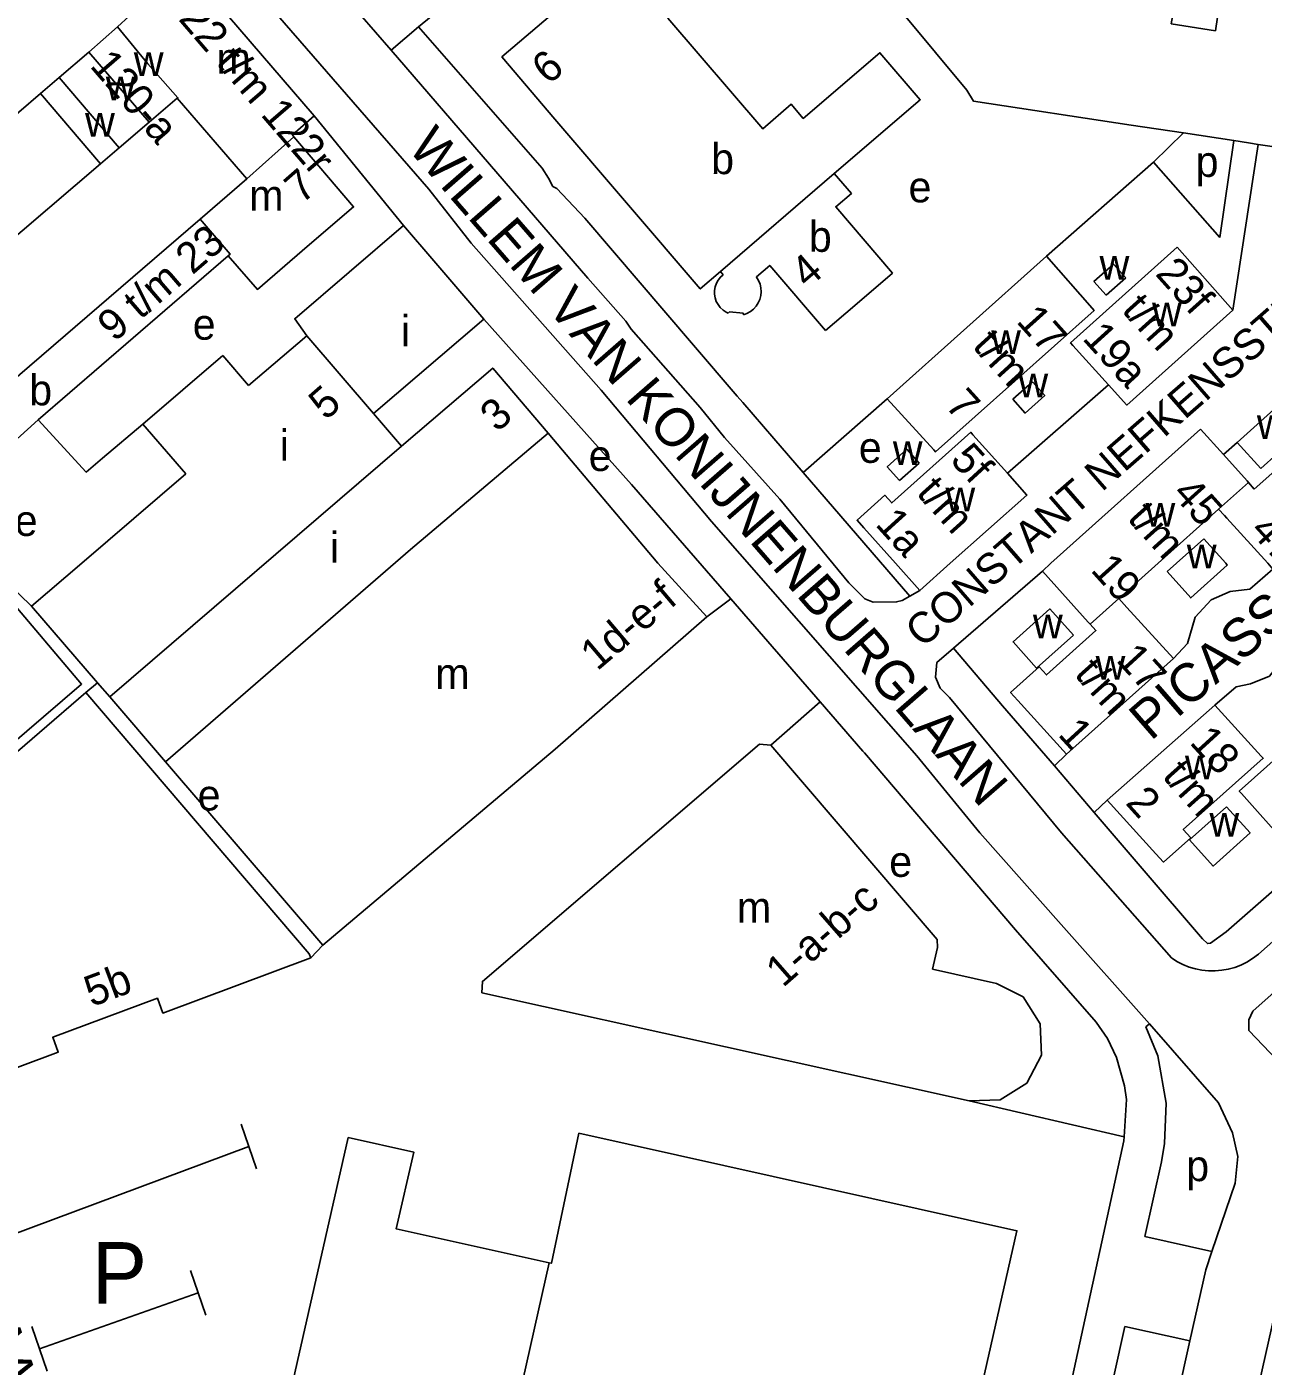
# Model space of a CAD drawing. Extents: x 161775 to 163181, y 382878 to 383925.
# Drawn here: x 162431.4 to 162592, y 383145.8 to 383319.7 of the extents above; entities that cross this region are included whole.
import ezdxf

# ---------------------------------------------------------------- set-up
doc = ezdxf.new("R2010")
doc.units = 0
for name, color, linetype in [('BLT_Basislijn', 7, 'Continuous'), ('BLT_Bebouwing', 7, 'Continuous'), ('BLT_Centroide', 7, 'Continuous'), ('BLT_Huisnummer', 7, 'Continuous'), ('BLT_Huisnummer_reeks', 7, 'Continuous'), ('BLT_Onderdoorgang_en_onderverdeling', 7, 'Continuous'), ('BLT_Onderverdeling_panden', 7, 'Continuous'), ('BLT_Straatnaam', 7, 'Continuous'), ('BLT_Tekst_parkeren', 7, 'Continuous')]:
    doc.layers.add(name, color=color, linetype=linetype)

msp = doc.modelspace()

# ---------------------------------------------------------------- linework, layer by layer
at = {"layer": 'BLT_Basislijn'}
for p, q in [((162478.7, 383316.62), (162482.27, 383319.63)), ((162482.27, 383319.63), (162483.91, 383321.01)), ((162468.7, 383308.09), (162480.34, 383293.87)), ((162581.62, 383305.87), (162577.71, 383302.07)), ((162588.15, 383304.88), (162586.35, 383292.29)), ((162591.33, 383304.39), (162588.01, 383282.86)), ((162563.81, 383289.88), (162577.71, 383302.07)), ((162586.35, 383292.29), (162577.71, 383302.07)), ((162571.86, 383273.18), (162558.75, 383261.69)), ((162528.4, 383266.19), (162524.37, 383270.88)), ((162532.21, 383261.77), (162543.15, 383271.37)), ((162588.58, 383265.7), (162586.81, 383264.11)), ((162532.21, 383261.77), (162546.09, 383245.74)), ((162563.29, 383249), (162551.73, 383238.99)), ((162547.38, 383246.48), (162546.09, 383245.74)), ((162519.72, 383243.06), (162522.82, 383245.41)), ((162440.59, 383234.49), (162439.08, 383233.21)), ((162528.04, 383226.39), (162534.45, 383232)), ((162566.44, 383225.23), (162564.87, 383223.71)), ((162571.72, 383219.27), (162570.01, 383217.65)), ((162469.83, 383200.43), (162468.27, 383198.8)), ((162553.79, 383180.2), (162573.92, 383175.56)), ((162460.22, 383174.28), (162459.22, 383177.17)), ((162460.22, 383174.28), (162429.02, 383162.66)), ((162461.23, 383171.4), (162460.22, 383174.28)), ((162578.75, 383172.29), (162576.61, 383162.62)), ((162576.61, 383162.62), (162585.3, 383160.64)), ((162584.5, 383158.27), (162585.3, 383160.64)), ((162453.66, 383155.3), (162452.65, 383158.19)), ((162582.43, 383149.04), (162584.5, 383158.27)), ((162566.26, 383031.23), (162594.26, 383156.08)), ((162453.66, 383155.3), (162433.05, 383148.01)), ((162454.66, 383152.41), (162453.66, 383155.3)), ((162433.05, 383148.01), (162432.04, 383150.9)), ((162574.02, 383150.93), (162582.43, 383149.04)), ((162434.05, 383145.12), (162433.05, 383148.01)), ((162564.33, 383068.3), (162582.43, 383149.04))]:
    msp.add_line(p, q, dxfattribs=at)
for points in [[(162461.02, 383337.08), (162463.62, 383334.28), (162470.56, 383326.03), (162478.7, 383316.62)], [(162577.2, 383190.23), (162565.75, 383203.12), (162555.18, 383215), (162546.98, 383225), (162520.33, 383255.43), (162505.98, 383272.47), (162489.13, 383291.55), (162483.6, 383298.59), (162460.49, 383325.18), (162458.18, 383327.64), (162456.06, 383330.26)], [(162574.82, 383306.9), (162554.33, 383310), (162553.46, 383311.42), (162545.35, 383321.19), (162545.63, 383322.33), (162548.32, 383324.44), (162552.73, 383328.57), (162552.67, 383329.15), (162551.02, 383331.07)], [(162482.27, 383319.63), (162498.33, 383301.28), (162499.14, 383300.01), (162499.73, 383298.93), (162500.25, 383298.66), (162503.86, 383294.82), (162517.99, 383278.32), (162523.66, 383271.7), (162524.37, 383270.88)], [(162546.09, 383245.74), (162545.09, 383245.18), (162544.36, 383244.99), (162541.31, 383244.97), (162540.22, 383245.4), (162538.15, 383247.47), (162529.18, 383258.32), (162522.03, 383266.33), (162518.84, 383270.23), (162509.9, 383280.38), (162509.2, 383281.43), (162504.26, 383287.03), (162478.7, 383316.62)], [(162581.62, 383305.87), (162574.82, 383306.9)], [(162588.15, 383304.88), (162581.62, 383305.87)], [(162591.33, 383304.39), (162590.04, 383304.6), (162588.15, 383304.88)], [(162595.15, 383303.79), (162594.61, 383303.88), (162591.33, 383304.39)], [(162522.82, 383245.41), (162509.93, 383260.25), (162490.74, 383281.7)], [(162446.49, 383268.07), (162441.22, 383263.66), (162439.71, 383262.34), (162439.11, 383261.84), (162432.86, 383268.63)], [(162528.4, 383266.19), (162532.21, 383261.77)], [(162419.52, 383256.55), (162432.03, 383244.45)], [(162570.01, 383217.65), (162576.23, 383210.37), (162584.08, 383201.25), (162584.73, 383200.63), (162585.13, 383200.67), (162587.16, 383202.14), (162600, 383213.42), (162644.34, 383252.93)], [(162591.34, 383199.25), (162600, 383206.93), (162614.36, 383219.68), (162636.52, 383239.9), (162642.31, 383245.08), (162642.78, 383245.3), (162643.76, 383246.45), (162645.08, 383250.55), (162644.5, 383252.69), (162644.34, 383252.93)], [(162580.33, 383237.65), (162582.12, 383239.57), (162583.14, 383243.01), (162585.21, 383245.27), (162587.69, 383246.34), (162590.24, 383246.63), (162593.23, 383249.26)], [(162534.45, 383232), (162522.82, 383245.41)], [(162598.61, 383243.21), (162594.86, 383239.96), (162594.52, 383237.55), (162592.77, 383235.34), (162590.32, 383234.35), (162588.47, 383233.98), (162585.68, 383231.57)], [(162551.73, 383238.99), (162549.59, 383237.14), (162549.43, 383235.22), (162550.02, 383233.78), (162551.23, 383232.58), (162565.79, 383215), (162580.04, 383198.76)], [(162551.73, 383238.99), (162558.1, 383231.49), (162564.87, 383223.71)], [(162540.18, 383225.4), (162539.99, 383225.63), (162534.45, 383232)], [(162570.27, 383190.42), (162559.78, 383202.42), (162540.18, 383225.4)], [(162564.87, 383223.71), (162570.01, 383217.65)], [(162580.04, 383198.76), (162580.77, 383198.3), (162581.54, 383197.9), (162582.34, 383197.59), (162583.17, 383197.34), (162584.01, 383197.18), (162584.87, 383197.09), (162585.73, 383197.08), (162586.59, 383197.16), (162587.44, 383197.31), (162588.27, 383197.54), (162589.08, 383197.85), (162589.85, 383198.23), (162590.58, 383198.68), (162591.34, 383199.25)], [(162590.09, 383189.33), (162590.09, 383190.72), (162590.62, 383191.84), (162594.57, 383195.37)], [(162573.92, 383175.56), (162574.21, 383180.4), (162573.97, 383182.15), (162572.92, 383185.86), (162571.76, 383188.3), (162570.27, 383190.42)], [(162578.75, 383172.29), (162579.15, 383174.67), (162579.38, 383179.93), (162578.29, 383186.07), (162576.73, 383189.82), (162577.2, 383190.23)], [(162585.3, 383160.64), (162588.31, 383169.51), (162588.68, 383173), (162588, 383176.05), (162586.16, 383179.94), (162577.2, 383190.23)], [(162597.4, 383181.68), (162590.09, 383189.33)], [(162573.92, 383175.56), (162573.88, 383175.03), (162553.06, 383079.48), (162552.67, 383077.71)], [(162574.02, 383150.93), (162557.55, 383076.64), (162556.13, 383070.15)]]:
    msp.add_lwpolyline(points, dxfattribs=at)
at = {"layer": 'BLT_Bebouwing'}
for p, q in [((162443.17, 383319.64), (162439.45, 383316.37)), ((162439.45, 383316.37), (162435.6, 383313.06)), ((162435.6, 383313.06), (162433.18, 383310.99)), ((162433.18, 383310.99), (162385.9, 383270.62)), ((162447.3, 383307.26), (162450.94, 383310.37)), ((162450.94, 383310.37), (162459.98, 383299.91)), ((162443.4, 383303.93), (162447.3, 383307.26)), ((162443.39, 383303.93), (162440.98, 383301.87)), ((162393.7, 383261.49), (162440.98, 383301.87)), ((162459.98, 383299.91), (162453.92, 383294.69)), ((162484.28, 383289.27), (162480.34, 383293.87)), ((162580.78, 383291.04), (162588.01, 383282.86)), ((162432.86, 383268.63), (162457.56, 383289.92)), ((162490.74, 383281.7), (162484.28, 383289.27)), ((162521.83, 383287.47), (162521.49, 383287.87)), ((162574.12, 383287.08), (162571.58, 383284.8)), ((162476.42, 383269.46), (162490.74, 383281.7)), ((162460.18, 383273.08), (162467.75, 383279.55)), ((162571.86, 383273.18), (162567.26, 383278.3)), ((162456.85, 383276.97), (162446.49, 383268.07)), ((162561.99, 383273.58), (162559.44, 383271.3)), ((162476.42, 383269.46), (162480.07, 383265.21)), ((162446.49, 383268.07), (162452.05, 383261.6)), ((162558.75, 383261.69), (162554.28, 383266.68)), ((162596.39, 383266.56), (162591.64, 383262.29)), ((162547.27, 383263.02), (162544.73, 383260.76)), ((162590.07, 383260.48), (162589.88, 383260.7)), ((162590.07, 383260.48), (162590.79, 383259.62)), ((162563.29, 383249), (162569.23, 383242.37)), ((162440.59, 383234.49), (162432.03, 383244.45)), ((162569.23, 383242.37), (162569.49, 383242.09)), ((162567.32, 383240.66), (162562.54, 383236.39)), ((162442.17, 383232.65), (162440.59, 383234.49)), ((162449.42, 383224.21), (162442.17, 383232.65)), ((162585.68, 383231.57), (162591.72, 383224.96)), ((162469.83, 383200.43), (162449.42, 383224.21)), ((162587.19, 383218.4), (162582.41, 383214.12))]:
    msp.add_line(p, q, dxfattribs=at)
for points in [[(162536.26, 383300.63), (162547.42, 383310.18), (162542.19, 383316.28), (162532.24, 383307.77), (162530.68, 383309.59), (162526.97, 383306.42), (162514.67, 383320.79), (162521.99, 383327.05), (162515.43, 383334.72), (162504.4, 383325.36), (162499.99, 383321.61), (162493.11, 383315.75), (162499.99, 383307.67), (162518.87, 383285.63), (162521.49, 383287.87)], [(162468.7, 383308.09), (162452.08, 383327.43), (162444.69, 383321.05), (162443.17, 383319.64)], [(162580.68, 383323.57), (162580.03, 383320.04), (162585.77, 383319.15), (162586.31, 383322.67)], [(162466.09, 383305.38), (162465.89, 383305.62), (162468.7, 383308.09)], [(162466.09, 383305.38), (162473.84, 383296.28), (162467.8, 383291.15), (162461.36, 383285.55), (162457.56, 383289.92)], [(162535.12, 383280.22), (162538.92, 383283.48), (162543.82, 383287.67), (162536.45, 383296.29), (162538.49, 383298.03), (162536.26, 383300.63)], [(162453.92, 383294.69), (162428.95, 383273.17), (162415.49, 383261.1)], [(162480.34, 383293.87), (162466.19, 383281.76), (162467.75, 383279.55)], [(162567.26, 383278.3), (162566.96, 383278.63), (162580.78, 383291.04)], [(162535.12, 383280.22), (162527.89, 383288.68), (162526.15, 383287.2)], [(162563.81, 383289.88), (162543.15, 383271.37)], [(162569.74, 383283.14), (162563.81, 383289.88)], [(162571.58, 383284.8), (162569.99, 383286.57), (162572.53, 383288.85), (162574.12, 383287.08)], [(162521.83, 383287.47), (162521.47, 383287.15), (162521.18, 383286.77), (162520.95, 383286.35), (162520.79, 383285.89), (162520.71, 383285.42), (162520.71, 383284.93), (162520.78, 383284.46), (162520.94, 383284), (162521.17, 383283.58), (162521.46, 383283.2), (162521.82, 383282.87), (162522.22, 383282.61), (162522.5, 383282.48)], [(162524.46, 383282.27), (162524.93, 383282.45), (162525.37, 383282.7), (162525.77, 383283.01), (162526.1, 383283.39), (162526.38, 383283.81), (162526.58, 383284.27), (162526.71, 383284.76), (162526.76, 383285.26), (162526.73, 383285.76), (162526.62, 383286.25), (162526.44, 383286.72), (162526.18, 383287.16), (162526.15, 383287.2)], [(162549.19, 383264.74), (162549.43, 383264.47), (162570, 383282.84), (162569.74, 383283.14)], [(162524.46, 383282.27), (162524.42, 383282.49), (162522.67, 383282.63), (162522.5, 383282.48)], [(162588.01, 383282.86), (162574.24, 383270.54), (162571.86, 383273.18)], [(162456.85, 383276.97), (162460.18, 383273.08)], [(162480.07, 383265.21), (162491.91, 383275.35), (162499.12, 383266.91)], [(162559.44, 383271.3), (162561.04, 383269.51), (162563.59, 383271.79), (162561.99, 383273.58)], [(162543.15, 383271.37), (162549.19, 383264.74)], [(162588.58, 383265.7), (162593.36, 383269.97)], [(162419.52, 383256.55), (162432.86, 383268.63)], [(162583.83, 383267.42), (162564.4, 383250), (162563.29, 383249)], [(162586.81, 383264.11), (162583.83, 383267.42)], [(162590.79, 383259.62), (162600, 383267.81), (162600.87, 383268.59)], [(162499.12, 383266.91), (162513.33, 383250), (162519.72, 383243.06)], [(162554.28, 383266.68), (162553.99, 383267.01), (162543.73, 383257.85), (162542.85, 383258.83), (162539.22, 383255.59), (162540.1, 383254.61)], [(162591.64, 383262.29), (162588.58, 383265.7)], [(162544.73, 383260.76), (162543.14, 383262.54), (162545.68, 383264.8), (162547.27, 383263.02)], [(162589.88, 383260.7), (162586.81, 383264.11)], [(162432.03, 383244.45), (162438.55, 383250), (162452.05, 383261.6)], [(162558.75, 383261.69), (162561.28, 383258.85), (162551.33, 383250), (162547.38, 383246.48)], [(162573.21, 383245.42), (162578.34, 383250), (162586.18, 383257.01)], [(162587.25, 383255.85), (162586.94, 383256.19), (162586.18, 383257.01)], [(162593.23, 383249.26), (162592.56, 383250), (162587.25, 383255.85)], [(162540.1, 383254.61), (162544.22, 383250), (162547.38, 383246.48)], [(162584.26, 383253.18), (162587.11, 383250), (162587.3, 383249.78), (162582.55, 383245.5), (162579.49, 383248.92)], [(162579.49, 383248.92), (162580.7, 383250), (162584.26, 383253.18)], [(162407.68, 383229.67), (162428.77, 383245.83), (162438.52, 383234.33), (162426.43, 383223.98), (162417.76, 383220.74), (162413.7, 383226.17), (162410.59, 383223.58)], [(162580.33, 383237.65), (162574.28, 383244.26), (162573.21, 383245.42)], [(162519.72, 383243.06), (162500, 383225.87), (162469.83, 383200.43)], [(162562.54, 383236.39), (162559.49, 383239.8), (162564.26, 383244.08), (162567.32, 383240.66)], [(162569.49, 383242.09), (162570.24, 383241.26), (162563.81, 383235.51), (162562.87, 383236.56), (162559.17, 383233.25), (162560.11, 383232.21)], [(162589.13, 383220.13), (162588.85, 383220.44), (162600, 383230.39), (162609.46, 383238.83), (162609.73, 383238.54)], [(162609.73, 383238.54), (162615.63, 383231.92), (162600, 383217.85), (162595.1, 383213.44), (162589.13, 383220.13)], [(162566.44, 383225.23), (162580.33, 383237.65)], [(162439.08, 383233.21), (162426.99, 383222.86), (162413.28, 383217.74)], [(162439.08, 383233.21), (162468.07, 383199.32), (162468.27, 383198.8)], [(162560.11, 383232.21), (162566.44, 383225.23)], [(162571.72, 383219.27), (162585.68, 383231.57)], [(162528.04, 383226.39), (162526.55, 383226.51), (162490.56, 383195.73), (162490.51, 383194.23)], [(162549.61, 383201.17), (162528.04, 383226.39)], [(162591.72, 383224.96), (162591.97, 383224.69), (162581.58, 383215.46), (162582.55, 383214.36), (162579.01, 383211.21), (162578.02, 383212.3)], [(162578.02, 383212.3), (162571.72, 383219.27)], [(162582.41, 383214.12), (162585.48, 383210.69), (162590.26, 383215), (162587.19, 383218.4)], [(162549.04, 383197.33), (162549.65, 383200.11), (162549.61, 383201.17)], [(162468.27, 383198.8), (162449.07, 383191.61), (162448.37, 383193.54), (162434.78, 383188.48), (162435.49, 383186.53), (162416.23, 383179.36), (162415.91, 383180.22), (162412.51, 383178.96), (162414.96, 383172.53), (162408.57, 383170.14), (162409.86, 383166.74), (162410.67, 383167.05), (162417.84, 383147.83), (162415.94, 383147.11), (162417.14, 383143.88)], [(162553.79, 383180.2), (162557.83, 383180.34), (162561.28, 383182.53), (162563.17, 383186.16), (162562.99, 383190.23), (162560.78, 383193.7), (162557.33, 383195.47), (162549.04, 383197.33)], [(162490.51, 383194.23), (162553.79, 383180.2)], [(162484.41, 383093.3), (162476.63, 383095.06), (162472.81, 383096.58), (162469.69, 383099.12), (162467.59, 383102.47), (162466.61, 383106.34), (162466.85, 383110.32), (162467.23, 383111.98), (162459.16, 383113.79), (162473.14, 383175.45), (162481.65, 383173.57), (162479.35, 383163.61), (162499.25, 383159.18)], [(162541.22, 383080.46), (162559.99, 383163.35), (162503.1, 383176.01), (162499.52, 383159.12), (162499.25, 383159.18)]]:
    msp.add_lwpolyline(points, dxfattribs=at)
at = {"layer": 'BLT_Onderdoorgang_en_onderverdeling'}
for p, q in [((162435.6, 383313.06), (162443.4, 383303.93)), ((162433.18, 383310.99), (162440.98, 383301.87))]:
    msp.add_line(p, q, dxfattribs=at)
at = {"layer": 'BLT_Onderverdeling_panden'}
for p, q in [((162447.13, 383314.84), (162443.17, 383319.64)), ((162447.3, 383307.26), (162439.45, 383316.37)), ((162466.09, 383305.38), (162459.98, 383299.91)), ((162536.26, 383300.63), (162521.49, 383287.87)), ((162467.75, 383279.55), (162476.42, 383269.46)), ((162442.17, 383232.65), (162480.07, 383265.21)), ((162586.18, 383257.01), (162590.07, 383260.48)), ((162569.49, 383242.09), (162573.21, 383245.42)), ((162499.25, 383159.18), (162484.41, 383093.3))]:
    msp.add_line(p, q, dxfattribs=at)
for points in [[(162450.94, 383310.37), (162451.03, 383310.45), (162447.13, 383314.84)], [(162453.92, 383294.69), (162457.83, 383290.15), (162457.56, 383289.92)], [(162499.12, 383266.91), (162481.23, 383251.8), (162449.42, 383224.21)]]:
    msp.add_lwpolyline(points, dxfattribs=at)

# ---------------------------------------------------------------- texts
at = {"layer": 'BLT_Centroide'}
for s, p in [('w', (162445.3, 383313.27)), ('m', (162456.05, 383313.55)), ('w', (162441.66, 383310.12)), ('w', (162438.97, 383305.38)), ('b', (162520.27, 383300.53)), ('p', (162583.19, 383300.17)), ('m', (162460.28, 383295.78)), ('e', (162545.91, 383296.86)), ('b', (162532.96, 383290.44)), ('w', (162570.72, 383286.81)), ('w', (162577.53, 383280.78)), ('e', (162452.95, 383279.03)), ('i', (162479.99, 383278.19)), ('w', (162556.64, 383277.19)), ('b', (162431.71, 383270.51)), ('w', (162560.17, 383271.53)), ('w', (162591.15, 383266.12)), ('i', (162464.25, 383263.34)), ('e', (162539.45, 383263.04)), ('w', (162543.87, 383262.78)), ('e', (162504.37, 383261.98)), ('w', (162550.7, 383256.75)), ('w', (162576.68, 383254.75)), ('e', (162429.83, 383253.55)), ('i', (162470.75, 383250.09)), ('w', (162582.05, 383249.34)), ('w', (162562.07, 383240.25)), ('w', (162570.2, 383234.91)), ('m', (162484.45, 383233.69)), ('w', (162581.81, 383221.94)), ('e', (162453.59, 383217.91)), ('w', (162584.99, 383214.53)), ('e', (162543.4, 383209.29)), ('m', (162523.62, 383203.34)), ('p', (162581.97, 383169.79))]:
    msp.add_text(s, height=4, dxfattribs=at).set_placement(p)
at = {"layer": 'BLT_Huisnummer'}
for s, rotation, p in [('6', 40.4039, (162499.15, 383312.02)), ('7', 41.1871, (162467.1, 383296.55)), ('4', 40.5479, (162532.79, 383285.57)), ('5', 41.1871, (162470.23, 383268.46)), ('3', 41.1871, (162492.49, 383266.91))]:
    msp.add_text(s, height=4, rotation=rotation, dxfattribs=at).set_placement(p)
at = {"layer": 'BLT_Huisnummer_reeks'}
for s, rotation, p in [('122 t/m 122r', 310.7566, (162449.05, 383322.86)), ('120-a', 310.7571, (162439.47, 383314.54)), ('9 t/m 23', 40.7579, (162442.77, 383278.64)), ('23f', 311.8068, (162577.84, 383287.51)), ('t/m', 311.9688, (162573.47, 383282.8)), ('17', 311.9589, (162559.79, 383281.36)), ('t/m', 312.2844, (162554.08, 383278.13)), ('19a', 312.2363, (162568.37, 383279.13)), ('7', 312.1943, (162550.53, 383270.41)), ('5f', 312.5209, (162551.18, 383263.32)), ('t/m', 311.8358, (162546.81, 383259.07)), ('45', 311.9589, (162580.02, 383258.94)), ('t/m', 311.8358, (162574.2, 383255.78)), ('1a', 312.1943, (162541.48, 383254.99)), ('47', 312.2363, (162590.11, 383254.13)), ('19', 311.8877, (162569.45, 383249.06)), ('1d-e-f', 40.318, (162505.47, 383235.94)), ('17', 312.5209, (162572.74, 383237.38)), ('t/m', 311.8358, (162567.32, 383235.54)), ('1', 312.5209, (162565.19, 383227.71)), ('18', 312.3972, (162582.29, 383226.67)), ('t/m', 311.8358, (162578.74, 383222.3)), ('2', 312.1346, (162573.97, 383218.83)), ('1-a-b-c', 41.1871, (162529.59, 383194.83)), ('5b', 20.4583, (162439.8, 383192.37))]:
    msp.add_text(s, height=4, rotation=rotation, dxfattribs=at).set_placement(p)
at = {"layer": 'BLT_Straatnaam'}
for s, height, rotation, p in [('WILLEM VAN KONIJNENBURGLAAN', 5, 311.0335, (162480.74, 383303.87)), ('CONSTANT NEFKENSSTRAAT', 4, 41.0619, (162547.71, 383238.89)), ('PICASSOHOF', 5, 41.0619, (162577.37, 383226.85)), ('KANAALDIJK-NOORD', 5, 288.9449, (162420.75, 383163.99))]:
    msp.add_text(s, height=height, rotation=rotation, dxfattribs=at).set_placement(p)
at = {"layer": 'BLT_Tekst_parkeren'}
msp.add_text('P', height=8, dxfattribs=at).set_placement((162439.87, 383153.87))

doc.saveas('drawing.dxf')
